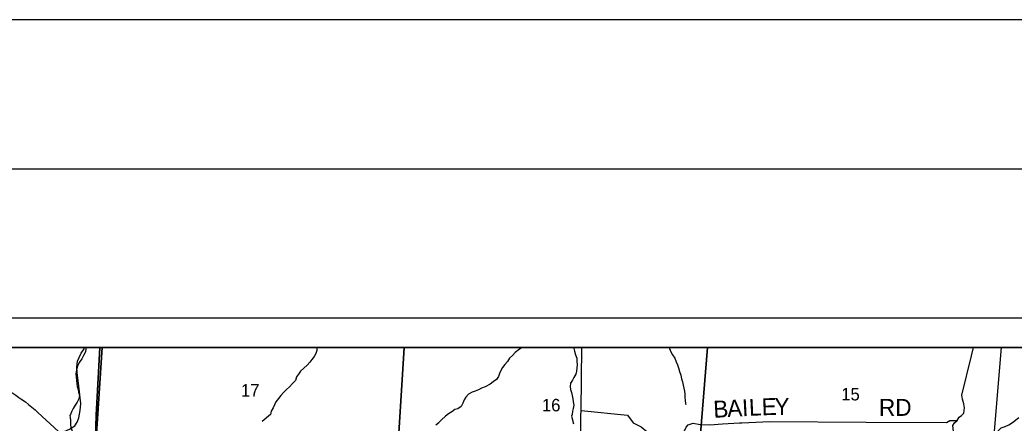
# Model space of a CAD drawing. Extents: x 0 to 40.8, y 0 to 22.
# Drawn here: x 3.414 to 6.756, y 20.647 to 22 of the extents above; entities that cross this region are included whole.
import ezdxf

# ---------------------------------------------------------------- set-up
doc = ezdxf.new("R2010")
doc.units = 0
for name, color, linetype in [('Default', 7, 'Continuous'), ('GM_X_County_Road', 7, 'Continuous'), ('GM_X_Minor_River', 7, 'Continuous'), ('GM_X_Section_Text', 7, 'Continuous'), ('GM_X_State_Route', 7, 'Continuous'), ('GM_X_Township_Road', 7, 'Continuous'), ('GM_X_Township_Road_Text', 7, 'Continuous'), ('SH_Border', 7, 'Continuous'), ('SH_Cut_Line', 7, 'Continuous'), ('SH_Data', 7, 'Continuous')]:
    doc.layers.add(name, color=color, linetype=linetype)

msp = doc.modelspace()

# ---------------------------------------------------------------- linework, layer by layer
at = {"layer": 'Default'}
msp.add_lwpolyline([(3.6829, 20.9), (2.1, 20.9), (2.1, 17.4153), (2.4594, 17.3966), (2.8463, 17.3693), (2.8484, 17.3691), (3.1244, 17.3534), (3.4481, 17.3334), (3.5638, 19.132), (3.5742, 19.2945), (3.575, 19.3064), (3.6386, 20.2396), (3.6672, 20.5588), (3.6703, 20.6733)], close=True, dxfattribs=at)
msp.add_lwpolyline([(7.7204, 20.9), (3.6829, 20.9), (3.6703, 20.6733), (3.6672, 20.5588), (3.6386, 20.2396), (3.575, 19.3064), (3.5742, 19.2945), (3.5638, 19.132), (3.4481, 17.3334), (4.5348, 17.2687), (4.8294, 17.2493), (5.3407, 17.2146), (5.6278, 17.197), (6.1785, 17.166), (6.9172, 17.1197)], dxfattribs=at)
at = {"layer": 'GM_X_County_Road'}
for points in [[(3.6903, 20.9), (2.7446, 20.9), (2.7045, 20.3832), (3.6475, 20.2502)], [(4.7052, 20.9), (3.6903, 20.9), (3.6475, 20.2502), (4.6616, 20.2002)], [(5.7251, 20.9), (4.7052, 20.9), (4.6616, 20.2002), (5.209, 20.2119), (5.6669, 20.1827)], [(6.7134, 20.9), (5.7251, 20.9), (5.6669, 20.1827), (6.1945, 20.1544), (6.6517, 20.1638)]]:
    msp.add_lwpolyline(points, close=True, dxfattribs=at)
msp.add_lwpolyline([(3.4084, 20.464), (3.4169, 20.4805), (3.4276, 20.4943), (3.4494, 20.5231), (3.4772, 20.5566), (3.4975, 20.5749), (3.5175, 20.59), (3.5432, 20.6081), (3.5625, 20.6182), (3.5807, 20.6257), (3.5982, 20.6368), (3.606, 20.6499), (3.6118, 20.6641), (3.6169, 20.6889), (3.619, 20.7128), (3.6158, 20.741), (3.6108, 20.78), (3.6063, 20.8149), (3.6057, 20.8342), (3.608, 20.8547), (3.6128, 20.8672), (3.6204, 20.8813), (3.6297, 20.8957), (3.631, 20.9)], dxfattribs=at)
at = {"layer": 'GM_X_Minor_River'}
for points in [[(3.6355, 20.9), (3.6359, 20.896), (3.6342, 20.8861), (3.6281, 20.8734), (3.6222, 20.8625), (3.6135, 20.8495), (3.6071, 20.8375), (3.6038, 20.8247), (3.6023, 20.8122), (3.6028, 20.8005), (3.6044, 20.789), (3.6056, 20.7788), (3.6065, 20.7689), (3.6093, 20.7593), (3.6113, 20.7498), (3.6144, 20.7391), (3.6126, 20.7281), (3.6063, 20.7173), (3.5996, 20.7068), (3.5925, 20.6956), (3.5877, 20.6848), (3.5836, 20.675), (3.5816, 20.6715)], [(4.4124, 20.9), (4.4117, 20.8906), (4.4083, 20.8796), (4.4031, 20.8698), (4.3951, 20.8603), (4.388, 20.8508), (4.3793, 20.8413), (4.3683, 20.8314), (4.3577, 20.8207), (4.3506, 20.8112), (4.3441, 20.8014), (4.3404, 20.7896), (4.3298, 20.7793), (4.32, 20.7687), (4.3098, 20.7592), (4.3, 20.7493), (4.2909, 20.7391), (4.283, 20.7292), (4.2743, 20.7178), (4.2701, 20.7075), (4.2649, 20.6973), (4.2584, 20.6866), (4.2558, 20.6756), (4.2285, 20.6517)], [(5.1021, 20.9), (5.0932, 20.8948), (5.0785, 20.883), (5.0702, 20.8731), (5.0596, 20.8647), (5.0528, 20.8533), (5.0441, 20.8435), (5.0366, 20.8336), (5.0302, 20.8233), (5.0264, 20.8131), (5.0226, 20.8032), (5.0158, 20.793), (5.0053, 20.7846), (4.9947, 20.7774), (4.9784, 20.7686), (4.9652, 20.7633), (4.955, 20.758), (4.9447, 20.7538), (4.9345, 20.75), (4.922, 20.7439), (4.9126, 20.734), (4.9069, 20.7241), (4.9028, 20.7139), (4.8968, 20.7025), (4.8862, 20.6945), (4.876, 20.6922), (4.8654, 20.6846), (4.8548, 20.6777), (4.845, 20.6694)], [(5.2762, 20.9), (5.2761, 20.897), (5.278, 20.8875), (5.2815, 20.8761), (5.2864, 20.8647), (5.2864, 20.853), (5.2876, 20.8431), (5.2861, 20.8313), (5.2846, 20.8207), (5.2824, 20.8105), (5.2756, 20.7998), (5.2714, 20.7903), (5.2646, 20.7805), (5.2635, 20.7691), (5.2643, 20.7588), (5.2685, 20.7493), (5.2704, 20.7395), (5.2727, 20.7281), (5.2738, 20.7179), (5.2758, 20.7065), (5.2739, 20.6955), (5.2716, 20.686), (5.2705, 20.6757), (5.2686, 20.6697)], [(5.5966, 20.9), (5.5976, 20.8971), (5.6021, 20.8861), (5.6082, 20.8759), (5.615, 20.8641), (5.6204, 20.852), (5.6242, 20.8425), (5.6276, 20.8323), (5.631, 20.8201), (5.6356, 20.8072), (5.6383, 20.7955), (5.641, 20.7849), (5.6433, 20.7735), (5.6463, 20.7636), (5.6482, 20.7538), (5.6494, 20.7435), (5.6494, 20.7333), (5.6498, 20.7223), (5.6517, 20.712), (5.6525, 20.7086)], [(3.2517, 20.805), (3.2623, 20.8063), (3.2737, 20.8045), (3.2835, 20.8031), (3.2936, 20.7998), (3.3045, 20.7972), (3.3151, 20.7939), (3.3278, 20.7871), (3.3382, 20.7811), (3.3479, 20.7748), (3.3576, 20.7674), (3.3683, 20.7595), (3.3784, 20.752), (3.39, 20.7464), (3.4, 20.7401), (3.4108, 20.7322), (3.4209, 20.7255), (3.4324, 20.718), (3.4424, 20.7094), (3.4539, 20.7004), (3.4647, 20.691), (3.4747, 20.6824), (3.5442, 20.618)], [(3.5816, 20.6715), (3.5833, 20.6653), (3.5835, 20.6555), (3.584, 20.6422), (3.5849, 20.6319), (3.5911, 20.6174), (3.6019, 20.6061), (3.6165, 20.596), (3.625, 20.5852), (3.6346, 20.5725), (3.6465, 20.5605), (3.6589, 20.5553), (3.6716, 20.563), (3.6873, 20.5722), (3.7018, 20.5768), (3.7152, 20.5842), (3.7279, 20.5915), (3.7389, 20.5947), (3.7511, 20.599), (3.7615, 20.6038), (3.774, 20.6054), (3.7853, 20.6014), (3.798, 20.5924)], [(4.8122, 20.6403), (4.8218, 20.6489), (4.8317, 20.6576), (4.845, 20.6694)], [(5.2686, 20.6697), (5.2745, 20.6439)], [(6.6884, 20.6109), (6.701, 20.6199), (6.7128, 20.6305), (6.7257, 20.6349), (6.7382, 20.6409), (6.7507, 20.6484), (6.7714, 20.6649)]]:
    msp.add_lwpolyline(points, dxfattribs=at)
at = {"layer": 'GM_X_State_Route'}
msp.add_lwpolyline([(5.299, 20.6159), (5.2997, 20.6699), (5.3001, 20.6888), (5.3024, 20.9)], dxfattribs=at)
at = {"layer": 'GM_X_Township_Road'}
for points in [[(6.7296, 20.3872), (6.7291, 20.401), (6.7239, 20.441), (6.7182, 20.4615), (6.7083, 20.473), (6.6817, 20.4879), (6.6156, 20.5288), (6.5874, 20.549), (6.5643, 20.5909), (6.5521, 20.6187), (6.5499, 20.6381), (6.5559, 20.6476), (6.5641, 20.6552), (6.5713, 20.6662), (6.5789, 20.6715), (6.5873, 20.6802), (6.5888, 20.698), (6.5874, 20.7117), (6.5825, 20.7273), (6.5802, 20.7398), (6.6125, 20.8725), (6.6197, 20.9)], [(5.3001, 20.6888), (5.4562, 20.6732), (5.4752, 20.6477), (5.5022, 20.6335), (5.5212, 20.6179), (5.5379, 20.6053), (5.5523, 20.5942), (5.5592, 20.5873), (5.5622, 20.5854), (5.5824, 20.5892), (5.6022, 20.5979), (5.6243, 20.6062), (5.6372, 20.613), (5.6479, 20.6202), (5.654, 20.6327), (5.6601, 20.6411), (5.6769, 20.6463), (5.7008, 20.6421), (5.7336, 20.6405), (5.7758, 20.6438), (5.8325, 20.6474), (5.8405, 20.6478)], [(5.8405, 20.6478), (5.9353, 20.652), (6.2591, 20.6492), (6.5286, 20.6488), (6.54, 20.6556), (6.5641, 20.6552)]]:
    msp.add_lwpolyline(points, dxfattribs=at)
at = {"layer": 'SH_Border'}
msp.add_lwpolyline([(1.5, 21.5), (33.5, 21.5), (33.5, 0.5), (1.5, 0.5)], close=True, dxfattribs=at)
at = {"layer": 'SH_Cut_Line'}
for points in [[(0, 0), (34, 0), (34, 22), (0, 22)], [(7.7204, 20.9), (2.1, 20.9), (2.1, 17.4153), (2.4594, 17.3966), (2.8463, 17.3693), (2.8484, 17.3691), (3.1244, 17.3534), (3.4481, 17.3334), (4.5348, 17.2687), (4.8294, 17.2493), (5.3407, 17.2146), (5.6278, 17.197), (6.1785, 17.166), (6.9172, 17.1197), (7.4495, 17.0841), (7.4798, 17.5479), (7.4963, 17.9476), (7.5246, 18.2047), (7.5789, 18.8336), (7.595, 19.0259), (7.6007, 19.1025), (7.6007, 19.1071), (7.6192, 19.376), (7.7055, 20.511)]]:
    msp.add_lwpolyline(points, close=True, dxfattribs=at)
at = {"layer": 'SH_Data'}
for p, q in [((2, 21), (9, 21)), ((2.1, 20.9), (8.9, 20.9))]:
    msp.add_line(p, q, dxfattribs=at)

# ---------------------------------------------------------------- texts
at = {"layer": 'GM_X_Section_Text'}
for s, p in [('17', (4.157, 20.7355)), ('15', (6.1749, 20.7226)), ('16', (5.1687, 20.6859))]:
    msp.add_text(s, height=0.04186, rotation=0, dxfattribs=at).set_placement(p)
at = {"layer": 'GM_X_Township_Road_Text'}
for s, height, rotation, p in [('B', 0.0568, 3.0534, (5.7463, 20.6641)), ('A', 0.0568, 3.0541, (5.7929, 20.6666)), ('I', 0.0568, 3.0534, (5.8428, 20.6692)), ('L', 0.0568, 2.8812, (5.866, 20.6705)), ('E', 0.0568, 1.7316, (5.9082, 20.6726)), ('Y', 0.0568, 0.2732, (5.9503, 20.6739)), ('RD', 0.05682, 0, (6.3016, 20.6708))]:
    msp.add_text(s, height=height, rotation=rotation, dxfattribs=at).set_placement(p)

doc.saveas('drawing.dxf')
